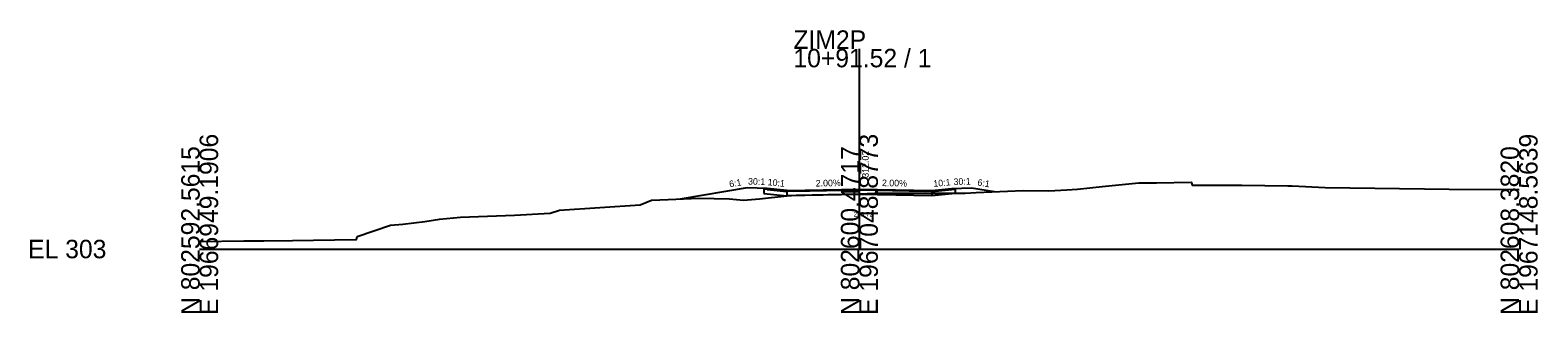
# Model space of a CAD drawing. Extents: x 1950845 to 1951408, y 736831 to 740365.
# Drawn here: x 1951179.2 to 1951407.7, y 737571.7 to 737614.6 of the extents above; entities that cross this region are included whole.
import ezdxf

# ---------------------------------------------------------------- set-up
doc = ezdxf.new("R2010")
doc.units = 0
for name, color, linetype in [('RD_GPK_XS_Cell', 7, 'Continuous'), ('RD_XS_Base', 7, 'Continuous'), ('RD_XS_EarthShd', 7, 'Continuous'), ('RD_XS_ExGround', 7, 'Continuous'), ('RD_XS_Pave', 7, 'Continuous'), ('RD_XS_PaveOvlay', 7, 'Continuous'), ('RD_XS_TieSlope', 7, 'Continuous'), ('RD_XS_TX_Elev_EX', 7, 'Continuous'), ('RD_XS_TX_Elev_PR', 7, 'Continuous'), ('RD_XS_TX_Slope', 7, 'Continuous')]:
    doc.layers.add(name, color=color, linetype=linetype)

msp = doc.modelspace()

# ---------------------------------------------------------------- linework, layer by layer
at = {"layer": 'RD_GPK_XS_Cell'}
for p, q in [((1951304.87, 737581.42), (1951304.87, 737611.8)), ((1951204.87, 737581.42), (1951304.87, 737581.42)), ((1951304.87, 737581.42), (1951404.87, 737581.42))]:
    msp.add_line(p, q, dxfattribs=at)
at = {"layer": 'RD_XS_Base'}
for points in [[(1951293.87, 737590.16), (1951290.87, 737590.46), (1951290.37, 737590.51)], [(1951290.37, 737590.51), (1951290.37, 737589.84)], [(1951290.37, 737589.84), (1951293.87, 737589.49)], [(1951293.87, 737590.16), (1951293.87, 737589.49)], [(1951315.87, 737589.5), (1951304.87, 737589.71), (1951293.87, 737589.49)], [(1951294.87, 737590.18), (1951304.87, 737590.38), (1951314.87, 737590.18)], [(1951315.87, 737590.16), (1951318.87, 737590.46), (1951319.37, 737590.51)], [(1951315.87, 737590.16), (1951315.87, 737589.49)], [(1951319.37, 737589.84), (1951315.87, 737589.49)], [(1951319.37, 737590.51), (1951319.37, 737589.84)]]:
    msp.add_lwpolyline(points, dxfattribs=at)
at = {"layer": 'RD_XS_EarthShd'}
for points in [[(1951290.87, 737590.61), (1951287.87, 737590.71)], [(1951318.87, 737590.61), (1951321.87, 737590.71)]]:
    msp.add_lwpolyline(points, dxfattribs=at)
at = {"layer": 'RD_XS_ExGround'}
msp.add_lwpolyline([(1951204.87, 737582.58), (1951211.56, 737582.66), (1951214.58, 737582.65), (1951218.93, 737582.73), (1951225.32, 737582.83), (1951228.66, 737582.87), (1951228.76, 737583.32), (1951233.81, 737585.02), (1951235.66, 737585.2), (1951239.01, 737585.61), (1951241.2, 737585.94), (1951244.42, 737586.28), (1951252.58, 737586.56), (1951258.01, 737586.84), (1951259.39, 737587.33), (1951271.64, 737588.13), (1951273.37, 737588.84), (1951275.9, 737588.94), (1951280.54, 737589.14), (1951285.17, 737589.05), (1951287.29, 737588.85), (1951289.71, 737589.04), (1951293.89, 737589.47), (1951295.28, 737589.58), (1951304.87, 737589.82), (1951307.14, 737589.88), (1951308.04, 737589.92), (1951308.82, 737589.91), (1951320.88, 737589.89), (1951322.56, 737590.01), (1951329.68, 737590.32), (1951333.58, 737590.27), (1951336.32, 737590.42), (1951337.95, 737590.51), (1951341.68, 737590.92), (1951347.21, 737591.46), (1951349.89, 737591.46), (1951355.21, 737591.55), (1951355.31, 737591.1), (1951358.01, 737591.13), (1951358.6, 737591.11), (1951362.83, 737591.12), (1951369.83, 737590.99), (1951370.49, 737590.99), (1951375.46, 737590.77), (1951394.25, 737590.53), (1951404.87, 737590.44)], dxfattribs=at)
at = {"layer": 'RD_XS_Pave'}
for points in [[(1951293.87, 737590.31), (1951290.87, 737590.61)], [(1951290.87, 737590.61), (1951290.87, 737590.46)], [(1951290.87, 737590.46), (1951293.87, 737590.16)], [(1951293.87, 737590.16), (1951293.87, 737590.31)], [(1951315.87, 737590.31), (1951318.87, 737590.61)], [(1951318.87, 737590.46), (1951315.87, 737590.16)], [(1951315.87, 737590.16), (1951315.87, 737590.31)], [(1951318.87, 737590.61), (1951318.87, 737590.46)]]:
    msp.add_lwpolyline(points, dxfattribs=at)
at = {"layer": 'RD_XS_PaveOvlay'}
for points in [[(1951293.87, 737590.31), (1951304.87, 737590.53), (1951315.87, 737590.31)], [(1951315.87, 737590.16), (1951304.87, 737590.38), (1951293.87, 737590.16)], [(1951293.87, 737590.31), (1951293.87, 737590.16)], [(1951315.87, 737590.31), (1951315.87, 737590.16)]]:
    msp.add_lwpolyline(points, dxfattribs=at)
at = {"layer": 'RD_XS_TieSlope'}
for points in [[(1951287.87, 737590.71), (1951277.68, 737589.01)], [(1951321.87, 737590.71), (1951325.37, 737590.13)]]:
    msp.add_lwpolyline(points, dxfattribs=at)

# ---------------------------------------------------------------- texts
at = {"layer": 'RD_GPK_XS_Cell'}
for s, p in [('ZIM2P', (1951294.87, 737611.8)), ('10+91.52 / 1', (1951294.87, 737609)), ('EL 303', (1951178.87, 737580.02))]:
    msp.add_text(s, height=2.8, dxfattribs=at).set_placement(p)
for s, p in [('E 1966949.1906', (1951207.67, 737571.42)), ('E 1967048.8773', (1951307.67, 737571.42)), ('E 1967148.5639', (1951407.67, 737571.42)), ('N 802592.5615', (1951204.87, 737571.42)), ('N 802600.4717', (1951304.87, 737571.42)), ('N 802608.3820', (1951404.87, 737571.42))]:
    msp.add_text(s, height=2.8, rotation=90, dxfattribs=at).set_placement(p)
at = {"layer": 'RD_XS_TX_Elev_EX'}
msp.add_text('220.72', height=0.7, dxfattribs=at).set_placement((1951304, 737586.34))
at = {"layer": 'RD_XS_TX_Elev_PR'}
msp.add_text('312.02', height=1, rotation=90, dxfattribs=at).set_placement((1951306.28, 737592.24))
at = {"layer": 'RD_XS_TX_Slope'}
for s, rotation, p in [('6:1', 9.4642, (1951285.22, 737590.78)), ('30:1', 358.0908, (1951287.98, 737591.21)), ('10:1', 354.2894, (1951290.93, 737591.11)), ('2.00%', 1.1458, (1951298.26, 737590.9)), ('2.00%', 358.8542, (1951308.28, 737590.97)), ('10:1', 5.7106, (1951316.13, 737590.84)), ('30:1', 1.9092, (1951319.16, 737591.12)), ('6:1', 350.5358, (1951322.71, 737591.08))]:
    msp.add_text(s, height=1, rotation=rotation, dxfattribs=at).set_placement(p)

doc.saveas('drawing.dxf')
